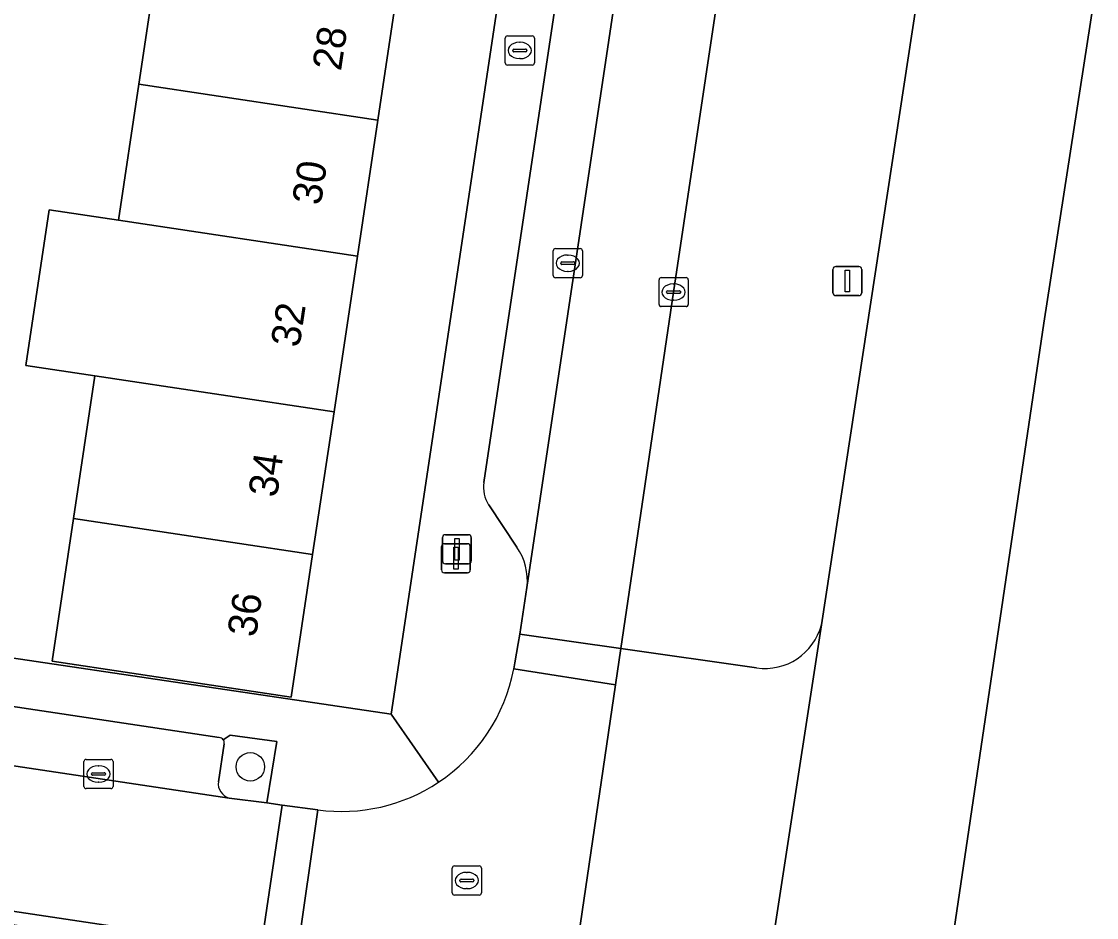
# Model space of a CAD drawing. Extents: x 164148 to 165261, y 382513 to 383432.
# Drawn here: x 164352.1 to 164389.02, y 382740.99 to 382771.75 of the extents above; entities that cross this region are included whole.
import ezdxf

# ---------------------------------------------------------------- set-up
doc = ezdxf.new("R2010")
doc.units = 0
for name, color, linetype in [('IMGEO_Boom', 7, 'Continuous'), ('IMGEO_Brandkraan', 7, 'Continuous'), ('IMGEO_Erf', 7, 'Continuous'), ('IMGEO_Groenvoorziening', 7, 'Continuous'), ('IMGEO_Kolk', 7, 'Continuous'), ('IMGEO_Lichtmast', 7, 'Continuous'), ('IMGEO_Pand', 7, 'Continuous'), ('IMGEO_Pand_nummerreeks', 7, 'Continuous'), ('IMGEO_Parkeervlak_open', 7, 'Continuous'), ('IMGEO_Rijbaan_lokaal_open', 7, 'Continuous'), ('IMGEO_Rioolput', 7, 'Continuous'), ('IMGEO_Voetpad_gesloten', 7, 'Continuous'), ('IMGEO_Voetpad_open', 7, 'Continuous')]:
    doc.layers.add(name, color=color, linetype=linetype)

msp = doc.modelspace()

# ---------------------------------------------------------------- linework, layer by layer
at = {"layer": 'IMGEO_Boom'}
msp.add_circle((164359.955, 382746.162), 0.489, dxfattribs=at)
at = {"layer": 'IMGEO_Brandkraan'}
for p, q in [((164368.711, 382770.33), (164368.711, 382771.182)), ((164368.786, 382771.256), (164369.638, 382771.256)), ((164369.712, 382771.182), (164369.712, 382770.33)), ((164369.199, 382771.036), (164369.224, 382771.036)), ((164368.97, 382770.75), (164368.97, 382770.762)), ((164369.408, 382770.713), (164369.01, 382770.713)), ((164369.013, 382770.799), (164369.411, 382770.799)), ((164369.222, 382770.476), (164369.197, 382770.476)), ((164369.454, 382770.762), (164369.454, 382770.75)), ((164369.638, 382770.256), (164368.786, 382770.256))]:
    msp.add_line(p, q, dxfattribs=at)
for points in [[(164368.711, 382770.33), (164368.711, 382771.182)], [(164368.786, 382771.256), (164369.638, 382771.256)], [(164369.712, 382771.182), (164369.712, 382770.33)], [(164369.638, 382770.256), (164368.786, 382770.256)]]:
    msp.add_lwpolyline(points, dxfattribs=at)
for centre, radius, start, end in [((164368.788, 382771.18), 0.0765, 91.552, 178.448), ((164368.788, 382771.18), 0.0765, 91.552, 178.448), ((164369.636, 382771.18), 0.0765, 1.552, 88.448), ((164369.636, 382771.18), 0.0765, 1.552, 88.448), ((164369.01, 382770.759), 0.0403, 85.8775, 175.7526), ((164369.007, 382770.749), 0.0366, 178.938, 274.7102), ((164369.411, 382770.756), 0.043, 264.8664, 352.4533), ((164369.415, 382770.761), 0.0386, 1.7309, 96.639), ((164368.788, 382770.332), 0.0765, 181.552, 268.448), ((164368.788, 382770.332), 0.0765, 181.552, 268.448), ((164369.636, 382770.332), 0.0765, 271.552, 358.448), ((164369.636, 382770.332), 0.0765, 271.552, 358.448)]:
    msp.add_arc(centre, radius, start, end, dxfattribs=at)
for centre, major_axis, ratio, start_param, end_param in [((164369.198, 382770.756), (-0.387, 0.002), 0.722429, 4.712389, 7.853982), ((164369.223, 382770.756), (-0.39, 0.002), 0.717154, 1.570796, 4.712389)]:
    msp.add_ellipse(centre, major_axis=major_axis, ratio=ratio, start_param=start_param, end_param=end_param, dxfattribs=at)
at = {"layer": 'IMGEO_Erf'}
for points in [[(164351.878, 382801.866), (164351.47, 382799.147), (164350.355, 382791.706), (164350.026, 382789.507), (164348.893, 382781.947), (164348.477, 382779.173), (164348.087, 382776.572), (164347.868, 382775.112), (164347.481, 382772.524), (164347.081, 382769.859), (164345.945, 382762.274), (164345.623, 382760.128), (164344.485, 382752.532), (164344.258, 382751.019), (164364.8, 382747.97), (164378.11, 382836.71)], [(164365.037, 382773.035), (164364.336, 382768.366), (164363.634, 382763.696), (164362.831, 382758.349), (164362.095, 382753.455), (164361.36, 382748.559), (164353.147, 382749.793), (164353.883, 382754.689), (164354.618, 382759.584), (164352.244, 382759.941), (164353.052, 382765.286), (164355.428, 382764.929), (164356.128, 382769.598), (164356.827, 382774.26)]]:
    msp.add_lwpolyline(points, dxfattribs=at)
at = {"layer": 'IMGEO_Groenvoorziening'}
for points in [[(164604.586, 382830.457), (164582.41, 382833.88), (164500.334, 382846.167), (164456.924, 382852.665), (164408.057, 382860.247), (164402.983, 382860.898), (164397.573, 382827.291), (164390.779, 382784.365), (164387.209, 382761.399), (164383.845, 382738.669), (164378.996, 382706.807)], [(164388.653, 382856.791), (164388.469, 382855.564), (164387.957, 382852.16), (164384.178, 382827.011), (164381.905, 382811.932), (164379.997, 382799.194), (164379.527, 382795.989), (164377.081, 382779.734), (164374.497, 382762.461), (164372.688, 382750.223), (164377.348, 382749.559)], [(164379.571, 382751.034), (164384.684, 382784.433), (164391.596, 382828.04)], [(164359.261, 382747.254), (164359.023, 382747.093)], [(164359.235, 382745.092), (164360.524, 382744.921), (164360.864, 382747.028), (164359.261, 382747.254)], [(164359.06, 382746.954), (164358.86, 382745.653)]]:
    msp.add_lwpolyline(points, dxfattribs=at)
for centre, radius, start, end in [((164377.627, 382751.551), 2.012, 262.0293, 345.1006), ((164358.869, 382746.978), 0.192, 352.9577, 36.8539), ((164359.362, 382745.583), 0.507, 172.0059, 255.5155)]:
    msp.add_arc(centre, radius, start, end, dxfattribs=at)
at = {"layer": 'IMGEO_Kolk'}
for p, q in [((164370.36, 382763.027), (164370.36, 382763.879)), ((164370.435, 382763.953), (164371.287, 382763.953)), ((164371.361, 382763.879), (164371.361, 382763.027)), ((164370.619, 382763.447), (164370.619, 382763.459)), ((164370.662, 382763.496), (164371.06, 382763.496)), ((164370.848, 382763.733), (164370.873, 382763.733)), ((164371.103, 382763.459), (164371.103, 382763.447)), ((164371.057, 382763.41), (164370.659, 382763.41)), ((164370.871, 382763.173), (164370.846, 382763.173)), ((164371.287, 382762.953), (164370.435, 382762.953)), ((164373.996, 382762.035), (164373.996, 382762.887)), ((164374.071, 382762.961), (164374.923, 382762.961)), ((164374.484, 382762.741), (164374.509, 382762.741)), ((164374.997, 382762.887), (164374.997, 382762.035)), ((164374.255, 382762.455), (164374.255, 382762.467)), ((164374.693, 382762.418), (164374.295, 382762.418)), ((164374.298, 382762.504), (164374.696, 382762.504)), ((164374.739, 382762.467), (164374.739, 382762.455)), ((164374.923, 382761.961), (164374.071, 382761.961)), ((164374.507, 382762.181), (164374.482, 382762.181)), ((164354.24, 382745.49), (164354.24, 382746.342)), ((164354.315, 382746.416), (164355.167, 382746.416)), ((164354.728, 382746.196), (164354.753, 382746.196)), ((164355.241, 382746.342), (164355.241, 382745.49)), ((164354.499, 382745.91), (164354.499, 382745.922)), ((164354.937, 382745.873), (164354.539, 382745.873)), ((164354.542, 382745.959), (164354.94, 382745.959)), ((164354.983, 382745.922), (164354.983, 382745.91)), ((164355.167, 382745.416), (164354.315, 382745.416)), ((164354.751, 382745.636), (164354.726, 382745.636))]:
    msp.add_line(p, q, dxfattribs=at)
for points in [[(164370.36, 382763.027), (164370.36, 382763.879)], [(164370.435, 382763.953), (164371.287, 382763.953)], [(164371.361, 382763.879), (164371.361, 382763.027)], [(164371.287, 382762.953), (164370.435, 382762.953)], [(164373.996, 382762.035), (164373.996, 382762.887)], [(164374.071, 382762.961), (164374.923, 382762.961)], [(164374.997, 382762.887), (164374.997, 382762.035)], [(164374.923, 382761.961), (164374.071, 382761.961)], [(164354.24, 382745.49), (164354.24, 382746.342)], [(164354.315, 382746.416), (164355.167, 382746.416)], [(164355.241, 382746.342), (164355.241, 382745.49)], [(164355.167, 382745.416), (164354.315, 382745.416)]]:
    msp.add_lwpolyline(points, dxfattribs=at)
for centre, radius, start, end in [((164370.437, 382763.877), 0.0765, 91.552, 178.448), ((164370.437, 382763.877), 0.0765, 91.552, 178.448), ((164371.285, 382763.877), 0.0765, 1.552, 88.448), ((164371.285, 382763.877), 0.0765, 1.552, 88.448), ((164370.659, 382763.456), 0.0403, 85.8775, 175.7526), ((164370.656, 382763.446), 0.0366, 178.938, 274.7102), ((164371.06, 382763.453), 0.043, 264.8664, 352.4533), ((164371.064, 382763.458), 0.0386, 1.7309, 96.639), ((164370.437, 382763.029), 0.0765, 181.552, 268.448), ((164370.437, 382763.029), 0.0765, 181.552, 268.448), ((164371.285, 382763.029), 0.0765, 271.552, 358.448), ((164371.285, 382763.029), 0.0765, 271.552, 358.448), ((164374.073, 382762.885), 0.0765, 91.552, 178.448), ((164374.073, 382762.885), 0.0765, 91.552, 178.448), ((164374.921, 382762.885), 0.0765, 1.552, 88.448), ((164374.921, 382762.885), 0.0765, 1.552, 88.448), ((164374.295, 382762.464), 0.0403, 85.8775, 175.7526), ((164374.292, 382762.454), 0.0366, 178.938, 274.7102), ((164374.696, 382762.461), 0.043, 264.8664, 352.4533), ((164374.7, 382762.466), 0.0386, 1.7309, 96.639), ((164374.073, 382762.037), 0.0765, 181.552, 268.448), ((164374.073, 382762.037), 0.0765, 181.552, 268.448), ((164374.921, 382762.037), 0.0765, 271.552, 358.448), ((164374.921, 382762.037), 0.0765, 271.552, 358.448), ((164354.317, 382746.34), 0.0765, 91.552, 178.448), ((164354.317, 382746.34), 0.0765, 91.552, 178.448), ((164355.165, 382746.34), 0.0765, 1.552, 88.448), ((164355.165, 382746.34), 0.0765, 1.552, 88.448), ((164354.539, 382745.919), 0.0403, 85.8775, 175.7526), ((164354.536, 382745.909), 0.0366, 178.938, 274.7102), ((164354.94, 382745.916), 0.043, 264.8664, 352.4533), ((164354.944, 382745.921), 0.0386, 1.7309, 96.639), ((164354.317, 382745.492), 0.0765, 181.552, 268.448), ((164354.317, 382745.492), 0.0765, 181.552, 268.448), ((164355.165, 382745.492), 0.0765, 271.552, 358.448), ((164355.165, 382745.492), 0.0765, 271.552, 358.448)]:
    msp.add_arc(centre, radius, start, end, dxfattribs=at)
for centre, major_axis, ratio, start_param, end_param in [((164370.847, 382763.453), (-0.387, 0.002), 0.722429, 4.712389, 7.853982), ((164370.872, 382763.453), (-0.39, 0.002), 0.717154, 1.570796, 4.712389), ((164374.483, 382762.461), (-0.387, 0.002), 0.722429, 4.712389, 7.853982), ((164374.508, 382762.461), (-0.39, 0.002), 0.717154, 1.570796, 4.712389), ((164354.727, 382745.916), (-0.387, 0.002), 0.722429, 4.712389, 7.853982), ((164354.752, 382745.916), (-0.39, 0.002), 0.717154, 1.570796, 4.712389)]:
    msp.add_ellipse(centre, major_axis=major_axis, ratio=ratio, start_param=start_param, end_param=end_param, dxfattribs=at)
at = {"layer": 'IMGEO_Lichtmast'}
for p, q in [((164379.969, 382762.441), (164379.969, 382763.241)), ((164379.969, 382763.241), (164379.969, 382762.441)), ((164380.069, 382763.341), (164380.859, 382763.341)), ((164380.859, 382763.341), (164380.069, 382763.341)), ((164380.959, 382763.241), (164380.959, 382762.441)), ((164380.959, 382762.441), (164380.959, 382763.241)), ((164380.859, 382762.341), (164380.069, 382762.341)), ((164380.069, 382762.341), (164380.859, 382762.341)), ((164366.556, 382753.232), (164366.556, 382754.032)), ((164366.556, 382754.032), (164366.556, 382753.232)), ((164366.622, 382753.824), (164367.412, 382753.824)), ((164367.412, 382753.824), (164366.622, 382753.824)), ((164366.656, 382754.132), (164367.446, 382754.132)), ((164367.446, 382754.132), (164366.656, 382754.132)), ((164367.546, 382754.032), (164367.546, 382753.232)), ((164367.546, 382753.232), (164367.546, 382754.032)), ((164366.522, 382752.924), (164366.522, 382753.724)), ((164366.522, 382753.724), (164366.522, 382752.924)), ((164367.512, 382753.724), (164367.512, 382752.924)), ((164367.512, 382752.924), (164367.512, 382753.724)), ((164367.446, 382753.132), (164366.656, 382753.132)), ((164366.656, 382753.132), (164367.446, 382753.132)), ((164367.412, 382752.824), (164366.622, 382752.824)), ((164366.622, 382752.824), (164367.412, 382752.824))]:
    msp.add_line(p, q, dxfattribs=at)
for points in [[(164380.389, 382763.216), (164380.539, 382763.216), (164380.539, 382762.466), (164380.389, 382762.466), (164380.389, 382763.216)], [(164366.976, 382754.007), (164367.126, 382754.007), (164367.126, 382753.257), (164366.976, 382753.257), (164366.976, 382754.007)], [(164366.942, 382753.699), (164367.092, 382753.699), (164367.092, 382752.949), (164366.942, 382752.949), (164366.942, 382753.699)]]:
    msp.add_lwpolyline(points, dxfattribs=at)
for centre, start, end in [((164380.069, 382763.241), 90, 180), ((164380.069, 382763.241), 90, 180), ((164380.859, 382763.241), 0, 90), ((164380.859, 382763.241), 360, 90), ((164380.069, 382762.441), 180, 270), ((164380.069, 382762.441), 180, 270), ((164380.859, 382762.441), 270, 0), ((164380.859, 382762.441), 270, 0), ((164366.622, 382753.724), 90, 180), ((164366.622, 382753.724), 90, 180), ((164366.656, 382754.032), 90, 180), ((164366.656, 382754.032), 90, 180), ((164367.412, 382753.724), 0, 90), ((164367.412, 382753.724), 360, 90), ((164367.446, 382754.032), 0, 90), ((164367.446, 382754.032), 360, 90), ((164366.656, 382753.232), 180, 270), ((164366.656, 382753.232), 180, 270), ((164367.446, 382753.232), 270, 0), ((164367.446, 382753.232), 270, 0), ((164366.622, 382752.924), 180, 270), ((164366.622, 382752.924), 180, 270), ((164367.412, 382752.924), 270, 0), ((164367.412, 382752.924), 270, 0)]:
    msp.add_arc(centre, 0.1, start, end, dxfattribs=at)
at = {"layer": 'IMGEO_Pand'}
for points in [[(164365.037, 382773.035), (164356.827, 382774.26), (164356.128, 382769.598), (164364.336, 382768.366)], [(164364.336, 382768.366), (164356.128, 382769.598), (164355.428, 382764.929), (164363.634, 382763.696)], [(164363.634, 382763.696), (164355.428, 382764.929), (164353.052, 382765.286), (164352.244, 382759.941), (164354.618, 382759.584), (164362.831, 382758.349)], [(164362.831, 382758.349), (164354.618, 382759.584), (164353.883, 382754.689), (164362.095, 382753.455)], [(164362.095, 382753.455), (164353.883, 382754.689), (164353.147, 382749.793), (164361.36, 382748.559)]]:
    msp.add_lwpolyline(points, close=True, dxfattribs=at)
at = {"layer": 'IMGEO_Parkeervlak_open'}
for points in [[(164379.235, 382831.014), (164367.98, 382755.927)], [(164369.459, 382752.322), (164377.452, 382805.647)], [(164368.144, 382755.157), (164369.108, 382753.708)], [(164358.889, 382747.172), (164341.064, 382749.85)], [(164340.132, 382747.95), (164359.235, 382745.092)], [(164358.86, 382745.653), (164359.06, 382746.954)]]:
    msp.add_lwpolyline(points, dxfattribs=at)
for centre, radius, start, end in [((164369.068, 382755.756), 1.102, 171.09, 212.9572), ((164367.482, 382752.559), 1.991, 353.1733, 35.2491), ((164358.862, 382746.973), 0.201, 36.6646, 82.2922), ((164358.869, 382746.978), 0.192, 352.9577, 36.8539), ((164359.362, 382745.583), 0.507, 172.0059, 255.5155)]:
    msp.add_arc(centre, radius, start, end, dxfattribs=at)
at = {"layer": 'IMGEO_Rijbaan_lokaal_open'}
for points in [[(164377.081, 382779.734), (164379.527, 382795.989), (164379.997, 382799.194), (164381.905, 382811.932), (164384.178, 382827.011), (164387.957, 382852.16), (164388.469, 382855.564), (164385.018, 382856.097), (164382.377, 382838.563), (164382.368, 382838.422), (164382.245, 382837.606), (164381.703, 382834.004), (164377.452, 382805.647), (164369.459, 382752.322), (164369.209, 382750.719), (164372.688, 382750.223), (164374.497, 382762.461)], [(164372.688, 382750.223), (164369.209, 382750.719), (164369.158, 382750.397), (164369.041, 382749.737), (164369.004, 382749.522), (164372.504, 382748.976)], [(164362.276, 382744.688), (164361.049, 382744.852), (164360.323, 382739.921), (164361.564, 382739.732)]]:
    msp.add_lwpolyline(points, close=True, dxfattribs=at)
for points in [[(164395.784, 382853.789), (164391.596, 382828.04), (164384.684, 382784.433), (164379.571, 382751.034), (164376.942, 382733.935), (164374.489, 382717.772), (164373.096, 382708.107), (164373.009, 382707.505)], [(164378.996, 382706.807), (164383.845, 382738.669), (164387.209, 382761.399), (164390.779, 382784.365)], [(164313.093, 382751.984), (164311.981, 382752.165), (164311.273, 382747.283), (164312.566, 382747.089), (164360.175, 382739.944), (164360.323, 382739.921), (164361.049, 382744.852), (164360.524, 382744.921), (164359.235, 382745.092), (164340.132, 382747.95)], [(164376.942, 382733.935), (164379.571, 382751.034)], [(164377.348, 382749.559), (164372.688, 382750.223), (164372.504, 382748.976), (164370.926, 382738.304), (164372.716, 382738.031), (164373.52, 382737.908)], [(164372.504, 382748.976), (164369.004, 382749.522)], [(164362.276, 382744.688), (164361.564, 382739.732), (164370.926, 382738.304), (164372.504, 382748.976)]]:
    msp.add_lwpolyline(points, dxfattribs=at)
for centre, radius, start, end in [((164377.627, 382751.551), 2.012, 262.0293, 345.1006), ((164363.105, 382750.636), 6.003, 303.5188, 349.3052), ((164363.1, 382750.642), 6.011, 262.1167, 303.5229)]:
    msp.add_arc(centre, radius, start, end, dxfattribs=at)
at = {"layer": 'IMGEO_Rioolput'}
for p, q in [((164366.968, 382742.76), (164367.82, 382742.76)), ((164366.893, 382741.834), (164366.893, 382742.686)), ((164367.381, 382742.54), (164367.406, 382742.54)), ((164367.894, 382742.686), (164367.894, 382741.834)), ((164367.152, 382742.254), (164367.152, 382742.266)), ((164367.59, 382742.217), (164367.192, 382742.217)), ((164367.195, 382742.303), (164367.593, 382742.303)), ((164367.636, 382742.266), (164367.636, 382742.254)), ((164367.82, 382741.76), (164366.968, 382741.76)), ((164367.404, 382741.98), (164367.379, 382741.98))]:
    msp.add_line(p, q, dxfattribs=at)
for points in [[(164366.968, 382742.76), (164367.82, 382742.76)], [(164366.893, 382741.834), (164366.893, 382742.686)], [(164367.894, 382742.686), (164367.894, 382741.834)], [(164367.82, 382741.76), (164366.968, 382741.76)]]:
    msp.add_lwpolyline(points, dxfattribs=at)
for centre, radius, start, end in [((164366.97, 382742.684), 0.0765, 91.552, 178.448), ((164366.97, 382742.684), 0.0765, 91.552, 178.448), ((164367.818, 382742.684), 0.0765, 1.552, 88.448), ((164367.818, 382742.684), 0.0765, 1.552, 88.448), ((164367.192, 382742.263), 0.0403, 85.8775, 175.7526), ((164367.189, 382742.253), 0.0366, 178.938, 274.7102), ((164367.593, 382742.26), 0.043, 264.8664, 352.4533), ((164367.597, 382742.265), 0.0386, 1.7309, 96.639), ((164366.97, 382741.836), 0.0765, 181.552, 268.448), ((164366.97, 382741.836), 0.0765, 181.552, 268.448), ((164367.818, 382741.836), 0.0765, 271.552, 358.448), ((164367.818, 382741.836), 0.0765, 271.552, 358.448)]:
    msp.add_arc(centre, radius, start, end, dxfattribs=at)
for centre, major_axis, ratio, start_param, end_param in [((164367.38, 382742.26), (-0.387, 0.002), 0.722429, 4.712389, 7.853982), ((164367.405, 382742.26), (-0.39, 0.002), 0.717154, 1.570796, 4.712389)]:
    msp.add_ellipse(centre, major_axis=major_axis, ratio=ratio, start_param=start_param, end_param=end_param, dxfattribs=at)
at = {"layer": 'IMGEO_Voetpad_gesloten'}
msp.add_lwpolyline([(164312.566, 382747.089), (164311.273, 382747.283), (164311.133, 382747.304), (164311.073, 382746.855), (164360.101, 382739.5), (164360.175, 382739.944)], close=True, dxfattribs=at)
at = {"layer": 'IMGEO_Voetpad_open'}
for points in [[(164385.178, 382859.221), (164380.889, 382859.124), (164381.369, 382858.602), (164378.331, 382838.195), (164378.11, 382836.71), (164364.8, 382747.97), (164366.42, 382745.631)], [(164367.98, 382755.927), (164379.235, 382831.014)], [(164369.108, 382753.708), (164368.144, 382755.157)], [(164369.004, 382749.522), (164369.041, 382749.737), (164369.158, 382750.397), (164369.209, 382750.719), (164369.459, 382752.322)], [(164366.42, 382745.631), (164364.8, 382747.97), (164344.258, 382751.019)], [(164341.064, 382749.85), (164358.889, 382747.172)], [(164359.023, 382747.093), (164359.261, 382747.254), (164360.864, 382747.028), (164360.524, 382744.921), (164361.049, 382744.852), (164362.276, 382744.688)]]:
    msp.add_lwpolyline(points, dxfattribs=at)
for centre, radius, start, end in [((164369.068, 382755.756), 1.102, 171.09, 212.9572), ((164367.482, 382752.559), 1.991, 353.1733, 35.2491), ((164363.105, 382750.636), 6.003, 303.5188, 349.3052), ((164358.862, 382746.973), 0.201, 36.6646, 82.2922), ((164363.1, 382750.642), 6.011, 262.1167, 303.5229)]:
    msp.add_arc(centre, radius, start, end, dxfattribs=at)

# ---------------------------------------------------------------- texts
at = {"layer": 'IMGEO_Pand_nummerreeks'}
for s, p in [('28', (164363.069, 382770.028)), ('30', (164362.376, 382765.414)), ('32', (164361.643, 382760.535)), ('34', (164360.869, 382755.385)), ('36', (164360.148, 382750.588))]:
    msp.add_text(s, height=1, rotation=81.4574, dxfattribs=at).set_placement(p)

doc.saveas('drawing.dxf')
